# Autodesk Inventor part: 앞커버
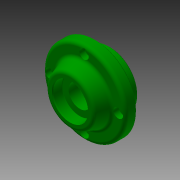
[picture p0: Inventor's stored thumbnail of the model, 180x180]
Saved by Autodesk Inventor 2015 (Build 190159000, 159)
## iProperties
Created: 2017-08
Part Number: 앞커버
Material: 알루미늄 6061
Document SubType Name: Modeling
Designer: mduedu
Density: 2.71 g/cm^3
Appearance: 알루미늄 - 평지
Author: mduedu
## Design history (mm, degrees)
sketch "스케치1"
  geometry: C1 r 35 at (0, 0); 1 further point
  constraints: 1 centre point, 1 coincident
  dimensions: "d0" = 70 diameter of C1
extrude "돌출1" new body sketch "스케치1" distance "d1" = 10; taper "d2" = 0 deg
sketch "스케치2"
  geometry: C1 r 24 at (0, 0); 1 further point
  constraints: 1 centre point, 1 coincident
  dimensions: "d3" = 48 diameter of C1
node "작업 평면1"
sketch "스케치3"
  geometry: C1 r 20 at (0, 0); 1 further point
  constraints: 1 centre point, 1 coincident
  dimensions: "d5" = 40 diameter of C1
feature "로프트1" sketch "스케치3" dims "d6" = 0, "d7" = 90 deg, "d8" = 0, "d9" = 90 deg
sketch "스케치4"
  geometry: C1 r 24 at (0, 0) reference; 1 further point
extrude "돌출2" join sketch "스케치4" distance "d10" = 12; taper "d11" = 0 deg
hole "구멍1" diameter "d14" = 40; stored, may be unused: countersink angle "d18" = 90 deg, drill point angle "d20" = 0 deg; dims "d12" = 10, "d13" = 10, "d15" = 6, "d16" = 4, "d17" = 2, "d19" = 12
hole "구멍2" diameter "d23" = 36; stored, may be unused: countersink angle "d27" = 90 deg, drill point angle "d29" = 0 deg; dims "d24" = 6, "d25" = 4, "d26" = 2, "d28" = 5, "d88" = 10, "d89" = 10
hole "구멍3" diameter "d32" = 19; stored, may be unused: countersink angle "d36" = 90 deg, drill point angle "d38" = 0 deg; dims "d30" = 10, "d31" = 10, "d33" = 6, "d34" = 4, "d35" = 2, "d37" = 3
chamfer "모따기1" distance "d39" = 1; stored, may be unused: second distance "d40" = 2, angle "d41" = 45 deg
sketch "스케치5"
  geometry: C1 r 15 at (0, 0); 1 further point
  constraints: 1 centre point, 1 coincident
  dimensions: "d42" = 30 diameter of C1
extrude "돌출3" cut sketch "스케치5" distance "d43" = 8.3; taper "d44" = 0 deg
chamfer "모따기2" distance "d47" = 0.8; stored, may be unused: second distance "d48" = 2, angle "d49" = 30 deg
fillet "모깎기1" dims "d50" = 0.3
fillet "모깎기2" dims "d51" = 0.3
fillet "모깎기3" dims "d52" = 3
sketch "스케치6" dims "d53" = 66
  geometry: C1 r 24 at (0, 0) reference; C2 r 35 at (0, 0) reference; 6 further points
  constraints: 2 vertical alignment, 1 coincident, 7 other
  dimensions: "d56" = 360 deg dimension on point (0, 0) point (0, 33) (derived)
sketch "스케치9"
  geometry: 4 further points
  constraints: 4 other
hole "구멍6" sketch "스케치9" at (-29, 0), (0, -29), (29, 0), (0, 29) diameter "d72" = 4.5; stored, may be unused: countersink angle "d76" = 90 deg, drill point angle "d78" = 0 deg; dims "d73" = 6, "d74" = 8, "d75" = 4.6, "d77" = 8
fillet "모깎기4" dims "d79" = 3
fillet "모깎기5" dims "d80" = 3
fillet "모깎기6" dims "d81" = 3
chamfer "모따기3" distance "d82" = 1; stored, may be unused: second distance "d83" = 2, angle "d84" = 30 deg
node "솔리드1"
other parameters: "d4" = 12
